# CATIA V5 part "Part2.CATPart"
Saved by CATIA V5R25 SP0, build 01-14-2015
Part number: Part2
Bounding box of the stored display mesh (mm): x -7.5 to 7.5, y -7.459 to 7.459, z 0 to 62.956
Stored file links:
  E:\1-Dersler\1-GÜZ\Tek Seç 7-Bilgisayar Destekli Mühendislik Analizi\KİNEMATİK ANALİZ\kinematik uygulama 9-03112025\Part2.CATPart
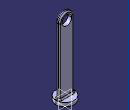
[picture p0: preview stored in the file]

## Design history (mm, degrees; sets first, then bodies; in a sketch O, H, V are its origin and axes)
Body1 (main body)
  Sketch1 on xy-plane, origin (0, 0, 0), H (1, 0, 0), V (0, 1, 0)
    circle A1 centre (0, 0) radius 7.5
    radius A1 = 7.5
  Pad1: profile Sketch1, direction (0, 0, 1), length 3
  Sketch2 on end face of Pad1, origin (0, 0, 3), H (1, 0, 0), V (0, 1, 0)
    line L1 (6, 1.5) -> (6, -1.5)
    line L2 (6, -1.5) -> (-6, -1.5)
    line L3 (-6, -1.5) -> (-6, 1.5)
    line L4 (-6, 1.5) -> (6, 1.5)
    length L4 = 12
    length L1 = 3
    vertical: L1 V, L3 V
    horizontal: L2 H, L4 H
    equidistance: L1 L3 O, L2 L4 O
  Pad2: profile Sketch2, direction (0, 0, 1), length 60
  TritangentFillet1: Face1 face of Pad2 from Sketch2.L3, Face2 face of Pad2 from Sketch2.L1, RemoveFace end face of Pad2
  Sketch3 on face of Pad2 from Sketch2.L4, origin (-2.8546, 1.5, 58.8249), H (1, 0, 0), V (0, 0, -1)
    point P1 (2.8546, 1.8249)
    reference projected arc E1 centre (2.8546, 1.8249) radius 6 from (-3.1454, 1.8249) to (8.8546, 1.8249) ccw from edge [face of Pad2 from Sketch2.L4 | face of TritangentFillet1]
    concentricity: E1 P1
  Hole1: placed by Sketch3, at (0, 1.5, 57) direction (0, -1, 0), diameter 8, depth 10, V-bottom angle 120
  Fillet1: radius 1, on edge [end face of Pad1 | face of Pad2 from Sketch2.L4]; edge [end face of Pad1 | face of Pad2 from Sketch2.L3]; edge [end face of Pad1 | face of Pad2 from Sketch2.L2]; edge [end face of Pad1 | face of Pad2 from Sketch2.L1]; edge [face of Pad2 from Sketch2.L1 | face of Pad2 from Sketch2.L2]; edge [face of Pad2 from Sketch2.L4 | face of Pad2 from Sketch2.L1]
